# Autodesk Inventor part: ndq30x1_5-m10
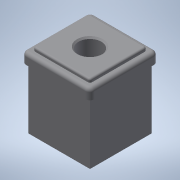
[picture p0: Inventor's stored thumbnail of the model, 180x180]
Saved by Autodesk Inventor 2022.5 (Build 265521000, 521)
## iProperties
Created: 2016-12
Part Number: ndq30x1_5-m10
Material: 一般
Document SubType Name: Modeling
Designer: imaocorp
Density: 1 g/cm^3
Appearance: 既定
Author: imaocorp
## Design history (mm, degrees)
node "ndq30x1_5-m10.x_t1"
node "ndq30x1_5-m10"
node "Base1"
